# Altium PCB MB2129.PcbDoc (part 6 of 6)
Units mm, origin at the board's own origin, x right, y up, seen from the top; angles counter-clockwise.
Board outline 70 x 133.34 mm, 6 copper layers (Top Layer, Signal Layer 1, Signal Layer 2, Signal Layer 3, Signal Layer 4, Bottom Layer), stack 1.57 mm thick; 377 components, 289 nets, 1482 pads, 1373 vias.
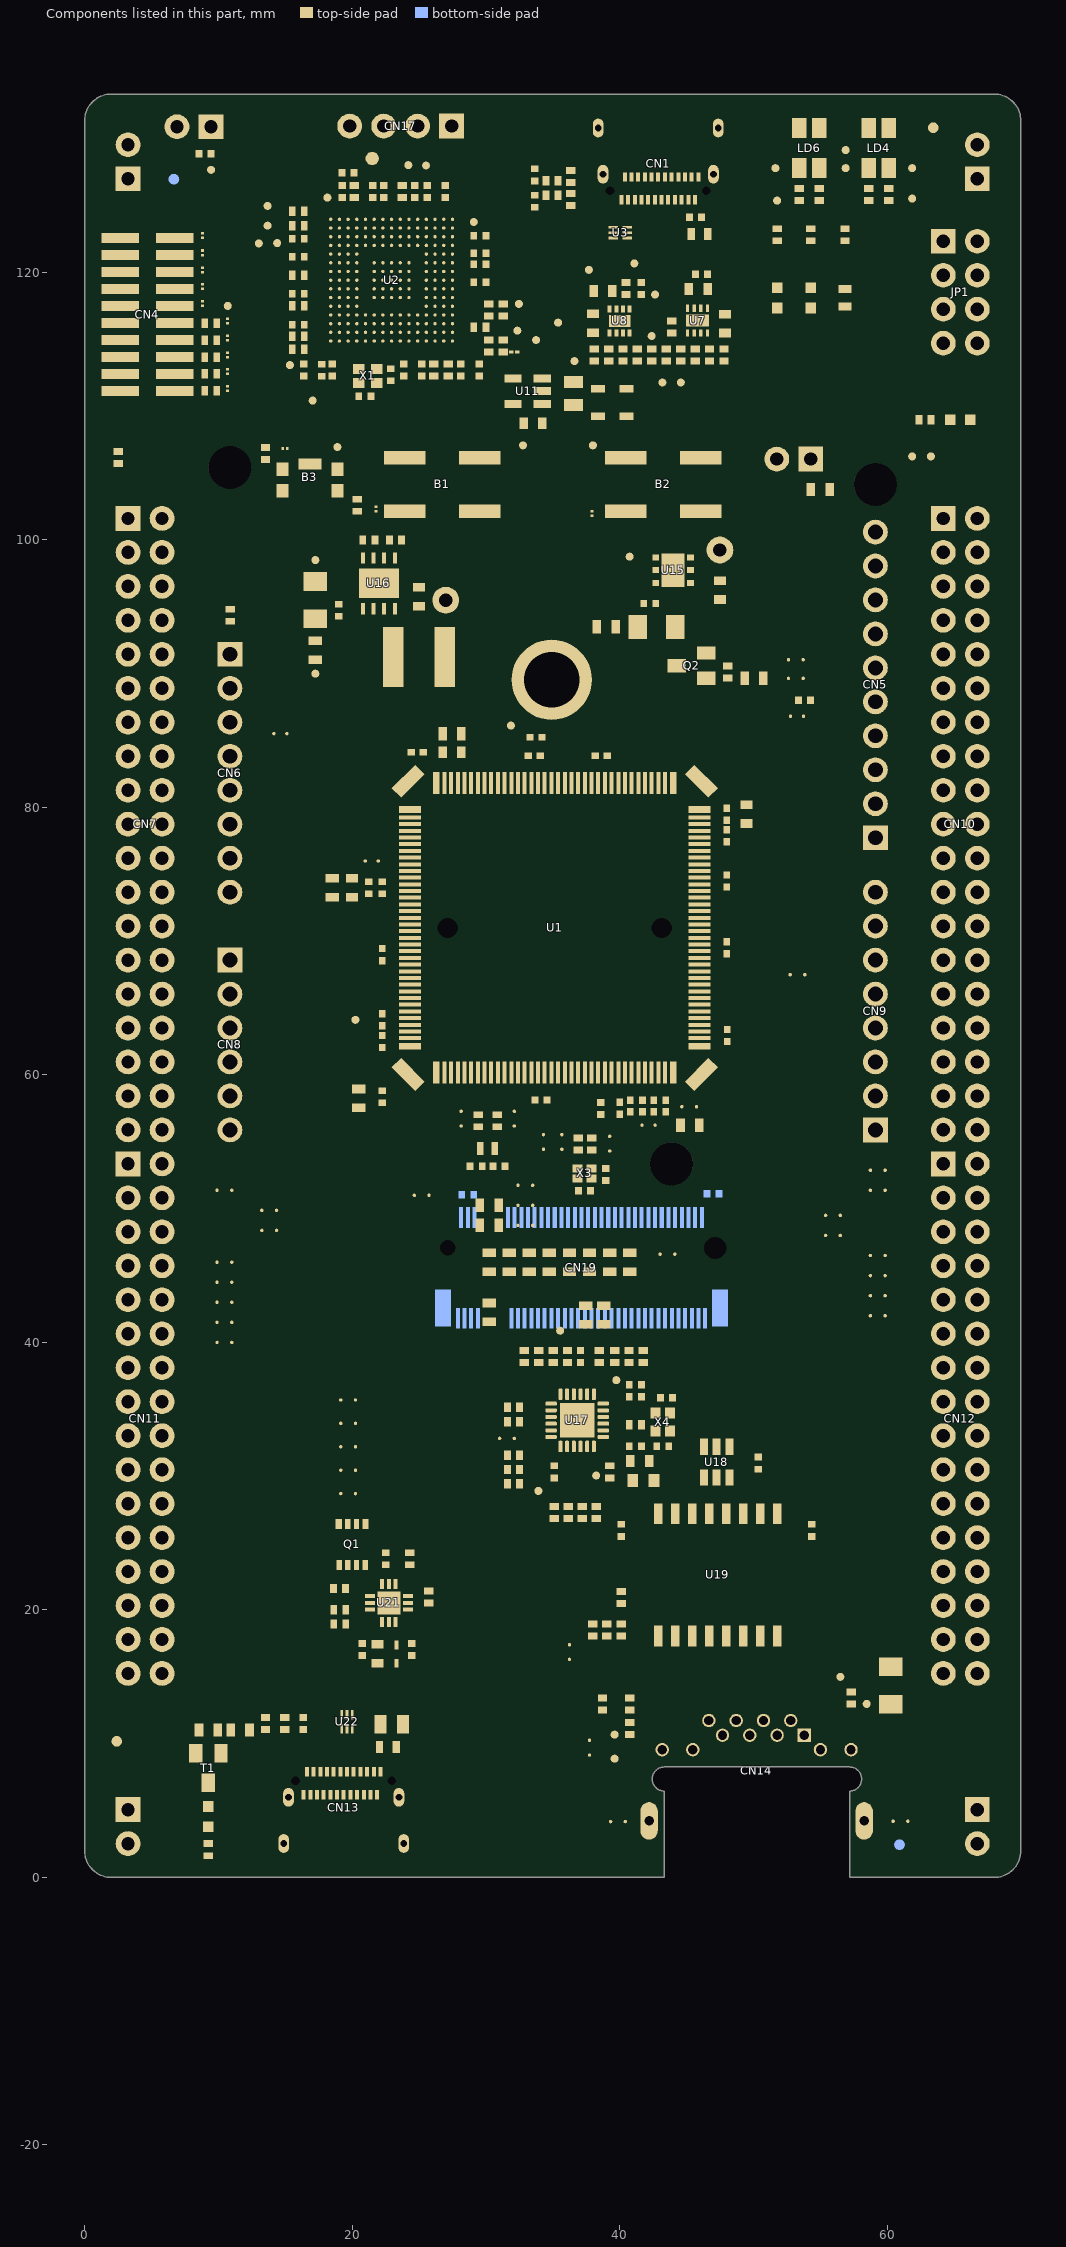
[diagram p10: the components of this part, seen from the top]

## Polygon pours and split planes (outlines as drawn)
GND on Top Layer "GND" (solid, remove dead copper, pour order 49): 38.349,-2.04 38.349,12.46 62.324,12.46 62.324,-2.04 72.124,-2.04 72.124,135.36 -1.001,135.36 -1.001,-2.04
VDD_MCU on Top Layer "VDDIO1_4_L01_P-001" (solid, remove dead copper, pour order 1): 49.75,80 50.25,80.5 50.25,81.75 50,82 49,82 48.75,81.75 48.75,80.5 49.25,80
NetC34_2 on Top Layer "NetC18_2" (solid, remove dead copper, pour order 9): 39.15,111.613 38.188,112.575 33.475,112.575 31.375,110.475 31.375,109.875 32.675,109.875 32.675,110.875 33.575,111.775 35.425,111.775 35.85,111.35 37.285,111.35 37.75,110.885 37.75,109.08 37.85,108.98 38.91,108.98 39.15,109.22
NetC43_2 on Top Layer "NetC30_2" (solid, remove dead copper, pour order 17): 39.5,93.25 40,92.75 42,92.75 42,96 42.6,96.6 42.95,96.6 42.95,97.95 41.45,97.95 39.5,96
GND on Top Layer "VDDIO1_4_L01_P-001" (solid, remove dead copper, pour order 48): 24.25,94.5 23,94.5 23,95.5 20.5,95.5 20,95 18.75,95 18.75,99 21,99 21,98 24.25,98
NetL2_1 on Top Layer "VDDIO1_4_L01_P-001" (solid, remove dead copper, pour order 2): 22.25,95.25 22.25,89.5 23.75,89.5 23.75,93.75 23.25,94.25 22.75,94.25 22.55,94.45 22.55,95.25
NetC44_2 on Top Layer "VDDIO1_4_L01_P-001" (solid, remove dead copper, pour order 47): 16.75,92.25 16.5,92.5 16.5,94.5 19.75,94.5 20,94.25 21.25,94.25 21.45,94.45 21.45,95.25 21.75,95.25 21.75,93.25 20.75,92.25
3V3 on Top Layer "5V_VIN" (solid, remove dead copper, pour order 18): 48.103,96.6 45.05,96.6 45.05,97.95 45.7,97.95 46.5,98.75 46.5,99.75 47.25,100.5 49.798,100.5 50.388,99.91 50.388,98.885
5V_VIN on Top Layer "5V_VIN" (solid, remove dead copper, pour order 15): 26,96.25 25.25,95.5 25,95.5 24.75,95.25 24.75,94.25 26.25,92.75 26.25,90.037 27.508,90.037 27.508,93.258 28,93.75 28,98.125 27.875,98.25 26.25,98.25 26,98
3V3 on Top Layer "3V3" (solid, remove dead copper, pour order 41): 0.675,85.902 2.793,85.902 2.793,68.875 0.675,68.875 0.675,85.899
5V_UCPD on Top Layer "5V_UCPD" (solid, remove dead copper, pour order 40): 21.7,20.875 21.7,21.825 20.525,23 20.525,23.75 18.825,23.75 18.825,22.651 20.601,20.875
5V on Top Layer "VIN" (solid, remove dead copper, pour order 31): 36.095,94.106 36.32,94.331 38.261,94.331 38.48,94.112 38.48,93.112 38.225,92.856 36.295,92.856 36.095,93.056
VIN on Top Layer "VIN" (solid, remove dead copper, pour order 14): 15.25,91.25 15.5,91.5 17.5,91.5 17.75,91.25 17.75,90 17.25,89.5 15.75,89.5 15.25,90
3V3_STLK on Top Layer "3V3_STLK" (solid, remove dead copper, pour order 12): 33.575,110.475 34.875,110.475 35.17,110.18 35.17,106.945 34.9,106.675 33.65,106.675 33.425,106.9 33.425,108.075 33.575,108.225
VBUS_STLK on Top Layer "VBUS_STLK" (solid, remove dead copper, pour order 8): 39.99,111.57 40.595,112.175 42.45,112.175 42.75,111.875 42.75,110.775 42.477,110.502 40.518,110.502 39.99,111.03
5V on Top Layer "5V" (solid, remove dead copper, pour order 7): 41.497,109.073 41.05,109.52 39.99,109.52 39.683,109.213 39.683,107.405 40,107.088 41.213,107.088 41.497,107.372
5V_STLK on Top Layer "5V_STLK" (solid, remove dead copper, pour order 6): 48.019,116.006 47.112,116.006 46.831,115.725 46.45,115.725 46.45,114.866 47.366,114.866 47.475,114.975 49.525,114.975 49.85,115.3 49.85,116.5 49.7,116.65 48.663,116.65
VBUS_STLK on Top Layer "VBUS_STLK" (solid, remove dead copper, pour order 5): 46.425,117.763 46.218,117.97 46.218,120.668 46.55,121 48.4,121 48.625,120.775 48.625,119.7 48.375,119.45 47.3,119.45 47.1,119.25 47.1,117.345 46.83,117.075 46.425,117.075
5V_STLK on Top Layer "5V_STLK" (solid, remove dead copper, pour order 4): 37.806,116.006 38.712,116.006 38.994,115.725 39.9,115.725 39.891,115.722 39.891,114.866 38.459,114.866 38.35,114.975 36.3,114.975 35.975,115.3 35.975,116.5 36.125,116.65 37.162,116.65
VBUS_STLK on Top Layer "VBUS_STLK" (solid, remove dead copper, pour order 3): 39.775,120.425 39.575,120.625 38.412,120.625 38.243,120.456 38.243,119.515 39.1,118.658 39.1,118.4 39.1,117.025 39.91,117.025 39.91,118.04 39.775,118.175
GND on Bottom Layer "C" (solid, remove dead copper, pour order 39): 38.4,-1.825 38.4,12.675 62.375,12.675 62.375,-1.825 72.175,-1.825 72.175,135.575 -0.95,135.575 -0.95,-1.825
SHGND on Bottom Layer "SHGND_L06_P019" (solid, remove dead copper, pour order 19): 41.547,13.675 59.275,13.675 59.275,0 41.647,0 41.547,0.004
3V3 on Bottom Layer "3V3" (solid, remove dead copper, pour order 32): 55.236,104.75 52.6,104.75 52.6,121.276 50.875,123.001 50.875,124.21 51.605,124.94 57.655,124.94 58.122,124.472 58.122,115.422 55.225,112.525 55.225,108.55
3V3 on Bottom Layer "3V3" (solid, remove dead copper, pour order 34): 0.675,85.902 2.793,85.902 2.793,68.875 0.675,68.875 0.675,85.899
5V_STLK on Bottom Layer "5V_STLK" (solid, remove dead copper, pour order 27): 62.45,123.85 63.775,125.175 68.509,125.175 69.325,124.359 69.325,92.403 66.072,92.403 65.159,93.316 65.159,120.556 64.739,120.975 62.975,120.975 62.45,121.5
GND on Signal Layer 1 "GND" (solid, remove dead copper, pour order 37): 38.4,-1.825 62.375,-1.825 72.175,-1.825 72.175,135.575 -0.95,135.575 -0.95,-1.825
AGND on Signal Layer 1 "AGND" (solid, remove dead copper, pour order 0): 39.25,61 41.05,61 41.05,59.325 41.15,59.225 42.325,59.225 42.425,59.125 42.425,57.023 42.748,56.7 42.745,56.697 42.745,55.35 39.781,55.35 39.25,55.881 39.25,59.475
5V on Signal Layer 3 "5V" (solid, remove dead copper, pour order 29): 11.65,95.6 11.275,95.225 11.275,94 12.271,93.004 12.271,83.661 11.21,82.6 4.625,82.6 4.625,80 14.725,80 14.725,91.05 15.425,91.75 18,91.75 18.575,91.175 18.575,89.025 31.025,89.025 34.75,92.75 38.75,92.75 41.113,95.1 41.113,105.093 42.396,106.375 47.375,106.375 49.3,108.3 68.95,108.3 68.95,123.6 65.725,123.6 65.725,113.275 62.8,110.35 48.275,110.35 46.525,108.6 39.933,108.6 38.75,107.417 38.75,98.15 36.2,95.6 29.35,95.6 28,94.25 26.25,94.25 24.9,95.6
3V3 on Signal Layer 3 "3V3" (solid, remove dead copper, pour order 38): 38.435,-0.074 38.435,14.426 62.41,14.426 62.41,-0.074 72.21,-0.074 72.21,137.326 -0.915,137.326 -0.915,-0.074
3V3_STLK on Signal Layer 3 "3V3_STLK" (solid, remove dead copper, pour order 28): 58.575,132.2 17.425,132.2 14.042,128.817 14.042,114.708 22.775,105.975 34.681,105.975 35.5,106.794 35.5,109.925 32.975,112.45 32.975,120.15 40.3,127.475 57.3,127.475 58.869,129.044 58.869,131.906
GND on Signal Layer 3 "NONET_L01_P-001" (solid, remove dead copper, pour order 50): 54.625,31.375 69.75,31.375 69.75,1.03 68.72,0 62.375,0 62.375,17.25 54.625,17.25
VDD_MCU on Signal Layer 3 "VDD_MCU" (solid, remove dead copper, pour order 25): 49.359,62.884 49.359,57.581 47.667,55.889 42.364,55.889 37.25,50.775 30.324,50.775 28.624,52.475 23.9,52.475 17.456,58.919 17.456,71.9 17.1,72.256 17.1,74.833 18.7,76.433 18.7,88.873 41.273,88.873 50.263,97.862 50.263,106.475 50.513,106.725 52.875,106.725 53.025,106.575 53.025,66.55
5V_UCPD on Signal Layer 3 "5V_UCPD" (solid, remove dead copper, pour order 30): 20.85,21.641 20.474,21.265 19.59,21.265 19.448,21.127 13.925,15.603 13.925,9.371 11.275,9.371 11.275,33.813 15.462,38 56.071,38 60.331,42.26 60.331,102.469 58.9,103.9 58.9,108.2 70,108.2 70,31.933 19.325,31.933 18.55,31.125 18.55,25.372 20.85,23.072
VIN on Signal Layer 3 "VIN" (solid, remove dead copper, pour order 26): 18.473,76.524 16.825,74.876 16.825,71.968 16.225,71.968 4.948,71.968 4.199,72.717 4.199,74.349 4.875,75.025 12.6,75.025 14.9,77.325 14.9,90.966 15.434,91.5 18,91.5 18.473,91.027 18.473,88.973
5V_VIN on Signal Layer 3 "5V_VIN" (solid, remove dead copper, pour order 20): 25.5,95 26,94.5 28,94.5 29.342,95.842 36.242,95.842 38.625,98.225 38.625,107.467 39.908,108.75 46.525,108.75 48.25,110.475 62.725,110.475 65.625,113.375 65.625,121 55.825,121 49.1,114.275 42.98,114.275 42.98,110.88 42.475,110.375 35.5,110.375 35.5,106.675 34.7,105.875 25.5,105.875
VBUSc on Signal Layer 3 "VBUSc" (solid, remove dead copper, pour order 22): 21.887,7.538 21.84,7.49 21.84,6.896 21.19,6.246 16.904,6.246 14.042,9.108 14.042,15.515 18.917,20.433 19.655,21.125 20.525,21.125 20.975,21.575 20.975,23.1 18.675,25.4 18.675,27.45 18.885,27.66 21.365,27.66 24.35,24.675 24.35,10
VBUS_STLK on Signal Layer 3 "VBUS_STLK" (solid, remove dead copper, pour order 23): 40.325,127.35 49.425,127.35 49.425,119.125 38.075,119.125 35.5,116.55 35.5,114.701 35.926,114.275 42.904,114.275 42.904,110.929 42.477,110.502 34.848,110.502 33.075,112.275 33.075,120.1
NetC88_2 on Signal Layer 3 "NetC79_2" (solid, remove dead copper, pour order 33): 33.466,31.825 45.8,31.825 54.125,31.825 54.125,25.818 52.245,25.818 52.245,28.125 42.42,28.125 42.42,25.95 35.357,25.95 33.466,27.842
5V_STLK on Signal Layer 3 "5V_STLK" (solid, remove dead copper, pour order 21): 49.06,114.4 55.785,121.125 66.15,121.125 66.15,123.775 59.283,123.775 58.683,123.175 49.573,123.175 49.573,119.016 38.141,119.016 35.625,116.5 35.625,114.78 36.005,114.4
GND on Signal Layer 4 "GND" (solid, remove dead copper, pour order 35): 38.4,-1.825 38.4,12.675 62.375,12.675 62.375,-1.825 72.175,-1.825 72.175,135.575 -0.95,135.575 -0.95,-1.825
GND on Signal Layer 2 "GND" (solid, remove dead copper, pour order 36): 38.4,-1.825 62.375,-1.825 72.175,-1.825 72.175,135.575 -0.95,135.575 -0.95,-1.825

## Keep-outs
Top Layer:
  circle w1.5: c66.1,105.725 r0.75
  circle w1.5: c29.325,18.7 r0.75
  circle w1.5: c10.8,98.375 r0.75
  circle w1.5: c15.4,71.175 r0.75
  circle w1.5: c65.55,10.125 r0.75
  circle w1.5: c4.525,10.125 r0.75
  circle w1.5: c59.125,49.05 r0.75
  circle w1.5: c10.8,49.05 r0.75
  circle w1.5: c54.325,71.125 r0.75
Bottom Layer:
  circle w1.5: c66.1,105.725 r0.75
  circle w1.5: c10.8,98.375 r0.75
  circle w1.5: c15.4,71.175 r0.75
  circle w1.5: c54.325,71.125 r0.75
  circle w1.5: c59.125,49.05 r0.75
  circle w1.5: c10.8,49.05 r0.75
  circle w1.5: c4.525,10.125 r0.75
  circle w1.5: c29.325,18.7 r0.75
  circle w1.5: c65.55,10.125 r0.75
  region: 8.125,105.429 8.125,105.437 cw(c10.858,105.437) 10.858,108.17 cw(c10.858,105.412) 13.616,105.412 cw(c10.879,105.412) 10.879,102.675 cw(c10.879,105.429)
  region: 56.385,104.159 56.385,104.167 cw(c59.118,104.167) 59.118,106.9 cw(c59.118,104.142) 61.876,104.142 cw(c59.139,104.142) 59.139,101.405 cw(c59.139,104.159)
  region: 41.145,53.359 41.145,53.367 cw(c43.878,53.367) 43.878,56.1 cw(c43.878,53.342) 46.636,53.342 cw(c43.899,53.342) 43.899,50.605 cw(c43.899,53.359)

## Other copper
Top Layer:
  pour cut-out: 32.309,123.767 31.582,124.494 ccw(c30.3,123.212) 30.3,125.025 27.679,125.025 ccw(c27.679,124.171) 27.075,124.775 ccw(c27.618,124.232) 26.85,124.232 26.85,123.654 ccw(c27.704,123.654) 27.1,123.05 27.244,122.906 ccw(c27.588,123.251) 27.588,122.763 ccw(c27.588,123.246) 27.93,122.905 28.212,123.187 ccw(c27.998,123.4) 28.3,123.4 cw(c29.085,123.4) 28.53,123.955 28.575,124 cw(c28.85,123.725) 28.85,124.114 30.135,124.114 cw(c30.135,122.717) 31.123,123.705 31.582,123.246
  pour cut-out: 19,18.48 19.15,18.48 19.15,19.213 19.139,19.224 19,19.224
  pour cut-out: 18.875,22.15 19.075,22.15 19.225,22 19.225,21.275 19.371,21.129 19.975,21.129 19.975,20.654 19.816,20.495 19.16,20.495 19.08,20.575 18.875,20.575
  pour cut-out: 26.2,21.375 26.195,21.37 26.195,20.15 24.875,20.15 24.67,20.355 24.67,21.295 24.8,21.425
  pour cut-out: 34.645,29.42 34.645,26.894 35.089,26.45 35.7,26.45 35.7,28.925 35.2,29.425
  pour cut-out: 44.325,34.1 44.245,34.02 44.245,32.045 43.925,31.725 41.975,31.725 41.55,31.3 41.225,31.3 41.225,30.05 41.025,29.85 40.525,29.85 40.175,30.2 39.2,30.2 39.1,30.1 39.1,28.48 38.65,28.03 37.92,28.03 37.45,28.5 37.45,30.4 39.7,32.65 41.02,32.65 41.975,32.65 41.975,33.25 41.845,33.38 39.82,33.38 39.7,33.5 39.7,34.325 40.1,34.725 43.125,34.725 43.75,34.1
  pour cut-out: 31.702,39.426 32.004,39.426 32.405,39.025 32.405,38.125 37.45,38.125 39.009,36.566 39.009,35.253 39.437,34.825 40,34.825 40,35.416 41.305,36.721 41.305,38.125 42.245,38.125 42.245,41.327 41.934,41.638 41.432,41.638 40.694,40.9 37.775,40.9 37.675,40.8 37.675,40.225 38.05,39.85 38.05,39.275 37.85,39.075 36.3,39.075 35.8,39.575 35.8,40.435 35.51,40.725 32.325,40.725 31.7,40.1 31.7,40
  pour cut-out: 31.25,35.62 31.25,28.955 33.804,28.955 33.925,29.076 33.925,35.35 33.655,35.62 32.9,35.62
  pour cut-out: 32.05,45.725 37.325,45.725 37.325,44.164 37.011,43.85 32.05,43.85
  pour cut-out: 40.25,56.775 40.775,56.25 41.548,56.25 41.548,58.022 41.445,58.125 40.425,58.125 40.25,57.95
  pour cut-out: 35.9,56.35 37.625,56.35 37.87,56.595 38.23,56.595 38.756,56.069 38.756,55.534 38.222,55 35.9,55
  pour cut-out: 32.125,58.1 30.975,58.1 30.85,57.975 30.85,57.125 31.245,56.73 32.358,56.73
  pour cut-out: 27.989,58.1 29.875,58.1 29.875,56.675 27.903,56.675
  pour cut-out: 30.5,49.975 30.5,48.38 30.76,48.12 34.07,48.12 34.33,48.38 34.33,50.12 34.2,50.25 30.775,50.25 30.625,50.1
  pour cut-out: 28.7,50 28.225,49.525 28.225,48.75 29.975,48.75 29.975,50
  pour cut-out: 22.5,23.12 22.6,23.02 22.6,22.325 21.384,22.325 20.967,22.741 20.975,22.749 20.975,23.125
  pour cut-out: 16.37,6.32 16.365,6.325 15.275,6.325 15.275,6.65 15.24,6.685 15.48,6.925 16.4,6.925
  pour cut-out: 25.35,62.55 28.472,62.55 29.512,61.51 29.769,61.51 29.769,60.969 29.5,60.7 25.5,60.7 25.325,60.875 25.35,60.9 25.35,62.4
  pour cut-out: 26.214,67.25 26.178,67.214 26.178,66.25 29.047,66.25 29.045,66.252 29.045,67.171
  pour cut-out: 4.082,71.772 4.229,71.625 6.198,71.625 6.87,70.954 6.87,67.477 6.668,67.275 4.561,67.275 4.082,67.754
  pour cut-out: 20.2,74.7 20.2,73.225 20.575,72.85 23.555,72.85 23.985,73.28 23.985,73.965 23.25,74.7
  pour cut-out: 21.73,79.929 21.73,77.028 21.858,76.9 23.5,76.9 23.5,79.6 23.171,79.929
  pour cut-out: 50.947,84.301 50.947,82.978 51.348,82.577 51.8,82.577 51.8,84.175 51.674,84.301
  pour cut-out: 50.145,78.628 50.625,78.628 50.625,78.325 50.617,78.317 50.145,78.317
  pour cut-out: 43.268,70.1 45.15,70.1 45.15,70.825 44.525,71.45 43.475,71.45 43.275,71.25
  pour cut-out: 27.295,84 27.725,84 27.725,84.895 27.735,84.905 28.615,84.905 28.615,83.56 28.65,83.525 29.31,83.525 29.75,83.085 29.75,82.65 27.25,82.65
  pour cut-out: 47.297,90.27 47.297,89.055 48.91,89.055 49.03,89.175 49.03,90.175 48.755,90.45 47.525,90.45
  pour cut-out: 41.112,98.526 41.112,97.963 41.2,97.875 41.405,98.08 43.115,98.08 43.15,98.045 43.15,96.5 42.725,96.5 42.146,95.921 42.146,95.803 42.172,95.803 42.245,95.73 42.575,95.73 42.575,95.925 43,96.35 43.45,96.35 43.45,98.181 43.105,98.526
  pour cut-out: 21.33,98.105 21.33,100.428 21.372,100.47 24.075,100.47 24.395,100.15 24.395,98.911 24.164,98.68 23.552,98.68 22.977,98.105 22.93,98.105
  pour cut-out: 18.26,94.92 18.34,95 20.135,95 20.53,95.395 21.33,95.395 21.32,95.385 21.32,94.504 19.93,94.504 19.804,94.63 18.26,94.63
  pour cut-out: 4.291,81.428 4.291,83.692 6.831,83.692 7,83.861 7,89.55 6.6,89.95 2.909,89.95 2.201,89.242 2.201,86.494 3.042,85.654 3.042,81.483 3.1,81.425
  pour cut-out: 43.284,111.355 44.749,111.355 44.97,111.576 44.97,113.075 44.92,113.125 43.275,113.125
  pour cut-out: 44.75,116.275 44.725,116.25 44.45,116.25 44.45,116.145 44.035,115.73 44.051,115.715 44.051,115.22 44.93,115.22 44.95,115.2 44.95,116.075
  pour cut-out: 45.485,125.44 45.51,125.415 45.51,124.765 46.125,124.15 46.125,123 44.209,123 43.849,123.36 43.278,123.36 43.2,123.438 43.2,125.005 43.635,125.44
  pour cut-out: 28.125,111.795 29.3,111.795 29.5,111.995 29.5,112.895 28.38,112.895 28.125,112.895
  pour cut-out: 15.92,112.375 17.88,112.375 18.005,112.5 18.005,113.345 17.55,113.8 15.17,113.8 15.17,113.142 15.577,112.736
  pour cut-out: 31.85,116.295 31.85,116.15 33.05,114.95 33.45,114.95 33.45,114.68 32.82,114.05 31.22,114.05 30.525,114.745 30.525,116.3
  pour cut-out: 29.7,124.225 29.7,123.405 29.875,123.23 29.875,119.146 30.446,118.575 31.7,118.575 31.7,118.487 31.85,118.337 31.85,116.295 31.65,116.495 29.68,116.495 29.275,116.9 29.4,117.025 29.4,124.225
  pour cut-out: 15.166,125.025 18.25,125.025 18.25,124.5 17.6,123.85 15.175,123.85
  pour cut-out: 15.776,123.15 15.65,123.024 15.65,121.585 15.78,121.455 16.17,121.455 16.17,123.146 16.166,123.15
  pour cut-out: 15.675,117.925 15.07,117.32 15.07,116.375 16.15,116.375 16.15,117.925
  pour cut-out: 39.25,19.7 39.25,22.625 52.225,22.625 52.225,18.43 62.375,18.43 62.375,0 38.447,0 38.447,15.678 37.175,16.95 37.175,19.7
  pour cut-out: 27.23,126.245 29.1,124.375 29.1,114.35 20.25,114.35 20.25,126.245
  text "1" at 26.793,1.334 h2 r90
  text ".Layer_Name" at 0.747,-16.422 h3
  text ".GTL" at 42.441,-16.422 h3
Signal Layer 1:
  text "2" at 26.793,2.584 h2 r90
  text ".Layer_Name" at 0.747,-16.422 h3
  text ".G1" at 42.441,-16.422 h3
Signal Layer 2:
  pour cut-out: 38.447,17.125 62.375,17.125 62.375,0 38.447,0
  text "3" at 26.793,4.084 h2 r90
  text ".Layer_Name" at 0.672,-16.422 h3
  text ".G2" at 42.366,-16.422 h3
Signal Layer 3:
  pour cut-out: 38.447,17.125 62.375,17.125 62.375,0 38.447,0
  text "4" at 26.793,6.334 h2 r90
  text ".Layer_Name" at 0.735,-16.418 h3
  text ".G3" at 42.43,-16.418 h3
Signal Layer 4:
  pour cut-out: 38.4,17.125 62.328,17.125 62.328,0 38.4,0
  text "5" at 26.793,7.834 h2 r90
  text ".Layer_Name" at 0.747,-16.422 h3
  text ".G4" at 42.441,-16.422 h3
Bottom Layer:
  pour cut-out: 30.086,46.98 31.829,46.98 31.829,44.889 32.172,44.546 32.796,44.546 34,45.75 35.65,45.75 35.65,45.725 36.329,45.046 36.329,44.23 36.325,44.226 36.325,43.55 36.346,43.55 36.61,43.285 37.495,44.17 38.795,44.17 38.795,45.347 38.49,45.652 38.49,47.435 36.873,49.052 29.555,49.052 29.555,47.511 29.915,47.151
  pour cut-out: 25.894,64.353 25.88,64.34 24.545,64.34 24.545,61.355 25.286,60.614 26.2,60.614
  pour cut-out: 38.506,13.601 38.506,17.125 62.256,17.125 62.256,13.601
  pour cut-out: 38.447,17.125 41.381,17.125 41.381,0 38.447,0
  pour cut-out: 62.365,0 59.431,0 59.431,17.125 62.365,17.125
  text "6" at 26.793,9.334 h2 r90
  text ".GBL" at 31.238,-16.454 h3
  text ".Layer_Name" at 72.552,-16.454 h3
Multi-Layer:
  pour cut-out: 42.42,28.125 42.42,17.125 52.245,17.125 52.245,28.125
  pour cut-out: 25.175,1.1 27.175,1.1 27.175,9.6 25.175,9.6

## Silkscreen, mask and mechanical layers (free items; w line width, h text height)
Top Overlay:
  circle w0.3: c51.95,102.775 r1.485
  region: 54.025,102.9 53.425,102.9 53.425,102.625 54.025,102.625
  rectangle: 49.875,102.625 50.475,102.9
  lines w0.12: 42.2,44.575 41.875,44.9 ; 42.2,45.225 41.875,44.9 ; 45.55,44.9 41.875,44.9 ; 45.55,45.875 45.55,43.3 54.425,43.3 ; 57.1,104.6 57.1,104.9 58.325,106.125 60.225,106.125 61,105.35 ; 0.625,115.494 0.625,118.25 1.12,118.25 1.12,125 8.28,125 8.28,108.875 1.12,108.875 1.12,115.494 0.625,115.494
  lines w0.25: 58.622,107.852 69.545,107.852 69.545,124.617 58.622,124.617 58.622,107.852
  lines w0.254: 50.324,115 58.622,115 ; 50.324,115 50.324,107.852 58.622,107.852 58.622,115 ; 50.324,115 58.622,115 ; 50.324,115 50.324,124.616 58.622,124.616 58.622,115
  text "PWR_STATUS" at 47.975,132.15 h1.4
  text "COM" at 57.85,132.075 h1.52
  text "GND" at 2,131.35 h1.52
  text "GND" at 65.226,131.328 h1.52
  text "STLK RST" at 11.55,129.7 h1.52
  text "USB STLINK" at 32.725,129.1 h1.52
  text "RESERVED" at 22.5,128.625 h1.4
  text "MIPI20" at 2.725,123.725 h1.52
  text "STLK" at 59.384,121.822 h1.4
  text "VIN" at 60.4,119.282 h1.4
  text "NRST" at 11.425,117.075 h1.5
  text "EXT" at 60.146,116.742 h1.4
  text "User LEDs" at 51.375,115.6 h1.4
  text "5V_SELECT" at 69.163,114.71 h1.4 r90
  text "USB1" at 59.375,114.1 h1.4
  text "5V" at 66.05,112.2 h1.4
  text "PWR_ON" at 63.3,110.05 h1.4
  text "BOOT0" at 14.85,107.6 h1.4
  text "USER" at 25,107.6 h1.52
  text "RESET" at 41.2,107.6 h1.52
  text "3V3" at 55.845,106.05 h1.4
  text "VDD MCU" at 47.7,104.9 h1.4
  text "IDD" at 47.775,102.65 h1.4
  text "A" at 51.225,102.05 h2.5
  text "SCL" at 54.916,100.15 h1.02
  text "3V3" at 48.425,100.067 h1.5
  text "SDA" at 54.829,97.61 h1.02
  text "AREF" at 54.069,95.07 h1.02
  text "5V_VIN" at 28.55,94.991 h1.5
  text "GND" at 54.819,92.53 h1.02
  text "NC" at 12.525,90.85 h1.02
  text "SCK" at 54.819,89.99 h1.02
  text "IOREF" at 12.45,88.506 h0.97
  text "MISO" at 54.768,87.352 h1.02
  text "NRST" at 12.475,86.4 h1
  text "~ MOSI" at 52.542,84.801 h1.7
  text "DIGITAL ~ PWM" at 62.307,83.42 h2 r90
  text "3V3" at 12.45,83.325 h1.02
  text "~ NSS" at 53.246,82.261 h1.7
  text "5V" at 12.45,80.8 h1.02
  text "POWER" at 8.967,79.771 h2 r90
  text "~ D9" at 54.416,79.721 h1.7
  text "GND" at 12.45,78.275 h0.97
  text "D8" at 55.83,77.29 h1.02
  text "GND" at 12.45,75.75 h0.97
  text "D7" at 55.83,73.162 h1.02
  text "VIN" at 12.45,72.975 h1.02
  text "~ D6" at 54.418,70.514 h1.7
  text "A0" at 12.634,68.033 h1.02
  text "~ D5" at 54.41,67.974 h1.7
  text "A1" at 12.634,65.686 h1.02
  text "D4" at 55.781,65.542 h1.02
  text "A2" at 12.634,63.029 h1.02
  text "~ D3" at 54.418,62.894 h1.7
  text "A3" at 12.634,60.591 h1.02
  text "D2" at 55.83,60.462 h1.02
  text "ANALOG" at 8.967,58.697 h2 r90
  text "A4" at 12.634,58.076 h1.02
  text "DIGITAL ~ PWM" at 62.307,58.02 h2 r90
  text "TX" at 55.936,57.922 h1.02
  text "A5" at 12.634,55.485 h1.02
  text "RX" at 55.83,55.382 h1.02
  text "32K" at 24.35,54.075 h1.4
  text "48M" at 41.025,50.125 h1.4
  text "J" at 15.95,40.225 h17.78
  text "MB2129D" at 16.45,39.35 h2.54
  text "L" at 54.1,32.55 h14
  text "ETH1" at 48.375,12.925 h1.52
  text "GND" at 1.853,7.122 h1.52
  text "GND" at 65.226,7.122 h1.52
  text "VBUS" at 11.025,3 h1.4 r90
  text "USB1" at 14.1,2.65 h1.52 r90
  text ".Layer_Name" at 0.747,-16.422 h3
  text ".GTO" at 42.441,-16.422 h3
Bottom Overlay:
  drawing of 66 lines, arcs and shapes, not listed
  text "GND" at 4.901,131.328 h1.52
  text "GND" at 68.274,131.328 h1.52
  text "C" at 57.5,113.875 h9
  text "F" at 26.791,113.25 h12
  text "S" at 35.886,113.25 h8
  text "G" at 47.625,113.25 h11
  text "H" at 31.375,104.6 h12
  text "I" at 42.975,104.2 h11
  text "CN10" at 67.049,104.12 h1.5
  text "CN7" at 5.852,104.02 h1.5
  text "1" at 63.743,102.948 h1.5 r270
  text "2" at 5.318,102.83 h1.5 r270
  text "2" at 66.168,102.83 h1.5 r270
  text "1" at 2.743,102.748 h1.5 r270
  text "CN5" at 57.556,102.17 h1.5
  text "PC10" at 1.725,100.975 h1.1 r315
  text "PC9" at 62.41,100.975 h1.1 r315
  text "PC11" at 8.45,100.95 h1.1 r315
  text "PF6" at 69.41,100.95 h1.1 r315
  text "SCL" at 57.523,100.15 h1.02
  text "PC12" at 1.725,98.435 h1.1 r315
  text "PF5" at 62.41,98.435 h1.1 r315
  text "PF15" at 8.45,98.41 h1.1 r315
  text "PD14" at 69.41,98.41 h1.1 r315
  text "SDA" at 57.523,97.61 h1.02
  text "3V3" at 1.725,95.895 h1.1 r315
  text "PG6" at 62.41,95.895 h1.1 r315
  text "PD15" at 69.41,95.87 h1.1 r315
  text "5V_EXT" at 8.825,95.295 h1.1 r315
  text "AREF" at 57.523,95.07 h1.02
  text "5V" at 69.425,94.2 h1.1 r315
  text "CN6" at 12.877,93.57 h1.5
  text "GND" at 8.45,93.33 h1.1 r315
  text "AREF" at 62.925,92.9 h1.1 r315
  text "STLK" at 69.4,92.8 h1.1 r315
  text "1" at 10.443,92.748 h1.5 r270
  text "GND" at 57.523,92.53 h1.02
  text "BOOT0" at 2.325,92.425 h1.1 r315
  text "NC" at 14.31,90.867 h1.02
  text "PG0" at 1.725,90.815 h1.1 r315
  text "GND" at 62.41,90.815 h1.1 r315
  text "PG1" at 8.45,90.79 h1.1 r315
  text "PE0" at 69.41,90.79 h1.1 r315
  text "SCK" at 57.523,89.99 h1.02
  text "IOREF" at 16.004,88.512 h0.97
  text "PB3" at 1.725,88.275 h1.1 r315
  text "PE12" at 62.41,88.275 h1.1 r315
  text "3V3" at 8.45,88.25 h1.1 r315
  text "NC" at 69.41,88.25 h1.1 r315
  text "MISO" at 57.523,87.352 h1.02
  text "NRST" at 16.017,86.407 h1
  text "PA13" at 1.725,85.735 h1.1 r315
  text "PE13" at 62.41,85.735 h1.1 r315
  text "NRST" at 8.45,85.71 h1.1 r315
  text "NC" at 69.41,85.71 h1.1 r315
  text "~ MOSI" at 57.65,84.806 h1.7
  text "DIGITAL ~ PWM" at 50.225,83.42 h2 r270
  text "3V3" at 15.113,83.332 h1.02
  text "PA14" at 1.725,83.195 h1.1 r315
  text "PE14" at 62.41,83.195 h1.1 r315
  text "3V3" at 8.45,83.17 h1.1 r315
  text "PE15" at 69.41,83.17 h1.1 r315
  text "~ NSS" at 57.65,82.266 h1.7
  text "5V" at 14.305,80.807 h1.02
  text "PA15" at 1.725,80.655 h1.1 r315
  text "PE11" at 62.41,80.655 h1.1 r315
  text "5V" at 8.45,80.63 h1.1 r315
  text "PB1" at 69.41,80.63 h1.1 r315
  text "POWER" at 17.56,79.771 h2 r270
  text "~ D9" at 57.65,79.726 h1.7
  text "GND" at 15.09,78.282 h0.97
  text "GND" at 1.725,78.115 h1.1 r315
  text "PF4" at 62.41,78.115 h1.1 r315
  text "GND" at 8.45,78.09 h1.1 r315
  text "GND" at 69.41,78.09 h1.1 r315
  text "D8" at 57.523,77.29 h1.02
  text "1" at 58.618,76.148 h1.5 r270
  text "GND" at 15.09,75.757 h0.97
  text "PG2" at 1.725,75.575 h1.1 r315
  text "PA9" at 62.41,75.575 h1.1 r315
  text "GND" at 8.45,75.55 h1.1 r315
  text "PF2" at 69.41,75.55 h1.1 r315
  text "D7" at 57.523,73.162 h1.02
  text "PA0" at 1.725,73.035 h1.1 r315
  text "PE9" at 62.41,73.035 h1.1 r315
  text "VIN" at 8.45,73.01 h1.1 r315
  text "PF14" at 69.41,73.01 h1.1 r315
  text "VIN" at 14.422,72.982 h1.02
  text "~ D6" at 57.65,70.518 h1.7
  text "PC14" at 1.725,70.495 h1.1 r315
  text "PF3" at 62.41,70.495 h1.1 r315
  text "PG4" at 8.45,70.47 h1.1 r315
  text "PB15" at 69.41,70.47 h1.1 r315
  text "1" at 10.218,69.823 h1.5 r270
  text "A0" at 14.315,68.04 h1.02
  text "~ D5" at 57.65,67.978 h1.7
  text "PC15" at 1.725,67.955 h1.1 r315
  text "PG15" at 62.41,67.955 h1.1 r315
  text "PA6" at 8.45,67.93 h1.1 r315
  text "PE10" at 69.41,67.93 h1.1 r315
  text "A1" at 13.88,65.693 h1.02
  text "D4" at 57.523,65.542 h1.02
  text "PH0" at 1.725,65.415 h1.1 r315
  text "PD3" at 62.41,65.415 h1.1 r315
  text "PA7" at 8.45,65.39 h1.1 r315
  text "PE8" at 69.41,65.39 h1.1 r315
  text "A2" at 14.315,63.036 h1.02
  text "~ D3" at 57.65,62.898 h1.7
  text "PH1" at 1.725,62.875 h1.1 r315
  text "PF1" at 62.41,62.875 h1.1 r315
  text "PA4" at 8.45,62.85 h1.1 r315
  text "AGND" at 69.41,62.85 h1.1 r315
  text "A3" at 14.315,60.598 h1.02
  text "D2" at 57.523,60.462 h1.02
  text "VBAT" at 1.725,60.335 h1.1 r315
  text "PA10" at 62.41,60.335 h1.1 r315
  text "PB0" at 8.45,60.31 h1.1 r315
  text "PF13" at 69.41,60.31 h1.1 r315
  text "ANALOG" at 17.56,58.697 h2 r270
  text "A4" at 14.364,58.083 h1.02
  text "DIGITAL ~ PWM" at 50.225,58.02 h2 r270
  text "TX" at 57.523,57.922 h1.02
  text "PC2" at 1.725,57.795 h1.1 r315
  text "PB4" at 62.41,57.795 h1.1 r315
  text "PF12" at 8.45,57.77 h1.1 r315
  text "PF8" at 69.41,57.77 h1.1 r315
  text "A5" at 14.315,55.492 h1.02
  text "RX" at 57.523,55.382 h1.02
  text "PC3" at 1.725,55.255 h1.1 r315
  text "PA8" at 62.41,55.255 h1.1 r315
  text "PF11" at 8.45,55.23 h1.1 r315
  text "PF9" at 69.41,55.23 h1.1 r315
  text "1" at 58.693,54.248 h1.5 r270
  text "PD11" at 1.725,52.715 h1.1 r315
  text "PB7" at 62.41,52.715 h1.1 r315
  text "NC" at 8.45,52.69 h1.1 r315
  text "PG10" at 69.41,52.69 h1.1 r315
  text "CN8" at 12.203,52.595 h1.5
  text "CN9" at 60.453,52.595 h1.5
  text "PD12" at 1.725,50.175 h1.1 r315
  text "PB6" at 62.41,50.175 h1.1 r315
  text "NC" at 8.45,50.15 h1.1 r315
  text "PG11" at 69.41,50.15 h1.1 r315
  text "PF7" at 1.725,47.635 h1.1 r315
  text "PG5" at 62.41,47.635 h1.1 r315
  text "NC" at 8.45,47.61 h1.1 r315
  text "PG9" at 69.41,47.61 h1.1 r315
  text "PD13" at 1.725,45.095 h1.1 r315
  text "PG13" at 62.41,45.095 h1.1 r315
  text "NC" at 8.45,45.07 h1.1 r315
  text "PD7" at 69.41,45.07 h1.1 r315
  text "PE7" at 1.725,42.555 h1.1 r315
  text "NC" at 62.41,42.555 h1.1 r315
  text "NC" at 8.45,42.53 h1.1 r315
  text "NC" at 69.41,42.53 h1.1 r315
  text "PD5" at 1.725,40.015 h1.1 r315
  text "MEM_LED1" at 62.41,40.015 h1.1 r315
  text "NC" at 8.45,39.99 h1.1 r315
  text "PG3" at 69.41,39.99 h1.1 r315
  text "PD6" at 1.725,37.475 h1.1 r315
  text "MEM_LED2" at 62.41,37.475 h1.1 r315
  text "NC" at 8.45,37.45 h1.1 r315
  text "PD10" at 69.41,37.45 h1.1 r315
  text "PC0" at 1.725,34.935 h1.1 r315
  text "MEM_GPIO" at 62.41,34.935 h1.1 r315
  text "NC" at 8.45,34.91 h1.1 r315
  text "PE4" at 69.41,34.91 h1.1 r315
  text "PB10" at 1.725,32.395 h1.1 r315
  text "NC" at 62.41,32.395 h1.1 r315
  text "NC" at 8.45,32.37 h1.1 r315
  text "PG7" at 69.41,32.37 h1.1 r315
  text "PD0" at 1.725,29.855 h1.1 r315
  text "NC" at 62.41,29.855 h1.1 r315
  text "NC" at 8.45,29.83 h1.1 r315
  text "NC" at 69.41,29.83 h1.1 r315
  text "PB2" at 1.725,27.315 h1.1 r315
  text "NC" at 62.41,27.315 h1.1 r315
  text "NC" at 8.45,27.29 h1.1 r315
  text "NC" at 69.41,27.29 h1.1 r315
  text "PF10" at 1.725,24.775 h1.1 r315
  text "NC" at 62.41,24.775 h1.1 r315
  text "NC" at 8.45,24.75 h1.1 r315
  text "NC" at 69.41,24.75 h1.1 r315
  text "PB5" at 1.725,22.235 h1.1 r315
  text "NC" at 62.41,22.235 h1.1 r315
  text "NC" at 8.45,22.21 h1.1 r315
  text "NC" at 69.41,22.21 h1.1 r315
  text "NC" at 1.725,19.695 h1.1 r315
  text "NC" at 62.41,19.695 h1.1 r315
  text "NC" at 8.45,19.67 h1.1 r315
  text "NC" at 69.41,19.67 h1.1 r315
  text "NC" at 1.725,17.155 h1.1 r315
  text "NC" at 62.41,17.155 h1.1 r315
  text "NC" at 8.45,17.13 h1.1 r315
  text "NC" at 69.41,17.13 h1.1 r315
  text "NC" at 1.725,14.615 h1.1 r315
  text "NC" at 62.41,14.615 h1.1 r315
  text "NC" at 8.45,14.59 h1.1 r315
  text "NC" at 69.41,14.59 h1.1 r315
  text "USB" at 20.628,13.518 h1.6
  text "ETHERNET" at 53.537,13.5 h1.6
  text "CN12" at 67.42,12.47 h1.5
  text "CN11" at 6.282,12.445 h1.5
  text "GND" at 4.774,7.122 h1.52
  text "GND" at 68.147,7.122 h1.52
  text ".GBO" at 31.238,-16.454 h3
  text ".Layer_Name" at 72.552,-16.454 h3
Top Paste:
  text ".Layer_Name" at 0.719,-16.412 h3
  text ".GTP" at 42.414,-16.412 h3
Bottom Paste:
  text ".GBP" at 31.129,-16.439 h3
  text ".Layer_Name" at 72.443,-16.439 h3
Top Solder:
  region: 25.175,9.6 25.175,1.1 27.175,1.1 27.175,9.6
  text ".Layer_Name" at 0.744,-16.487 h3
  text ".GTS" at 42.439,-16.487 h3
Bottom Solder:
  region: 25.175,9.6 25.175,1.1 27.175,1.1 27.175,9.6
  text ".GBS" at 31.154,-16.514 h3
  text ".Layer_Name" at 72.468,-16.514 h3
M1-Board Shape:
  lines w0.1: 68,0 ccw(c68,2) 70,2 70,131.34 ccw(c68,131.34) 68,133.34 2,133.34 ccw(c2,131.34) 0,131.34 0,2 ccw(c2,2) 2,0 40.22,0 43.345,0 43.345,6.458 cw(c43.345,7.358) 42.445,7.358 cw(c43.345,7.358) 43.345,8.258 57.192,8.257 cw(c57.192,7.357) 58.092,7.357 cw(c57.192,7.357) 57.192,6.457 57.192,0 68,0 ; 68,0 68,0
M2-Board Dimensions:
  text ".Layer_Name" at 0.747,-16.422 h3
  text ".GM2" at 42.441,-16.422 h3
M14-Top Assembly:
  text ".Layer_Name" at 0.747,-16.422 h3
  text ".GM14" at 42.441,-16.422 h3
M15-Bottom Assembly:
  text ".GM15" at 31.238,-16.454 h3
  text ".Layer_Name" at 72.552,-16.454 h3
Drill Drawing:
  drawing of 678 lines, arcs and shapes, not listed
  text "THE COMPONENTS WITH PLATED THROUGH HOLE (PTH) MAY BE WELDED (CABLED) IN \"PIN-IN-PASTE\" MODE (IF NECESSARY)" at -15.075,189.275 h3.5
  text "PCB SPECIFICATIONS :" at -14.039,182.104 h3
  text "PCB : TYPE 3" at 144.498,180.872 h3
  text "A.   MATERIAL :" at -14.039,178.104 h3
  text "FR-4" at 24.461,178.104 h3
  text "TG-170" at 40.961,178.104 h3
  text "X  TG-150" at 59.211,178.104 h3
  text "TG-140" at 75.211,178.104 h3
  text "ASPECT-RATIO, AXE Z :" at 144.498,175.372 h3
  text "B.   MATERIAL FAMILY :" at -14.039,175.104 h3
  text "N/A" at 24.461,175.104 h3
  text "C.   SOLDERMASK COLOR :" at -14.039,172.104 h3
  text "GREEN" at 24.461,172.104 h3
  text "X  WHITE" at 40.961,172.104 h3
  text "RED" at 59.211,172.104 h3
  text "BLACK" at 75.211,172.104 h3
  text "D.   SILKSCREEN COLOR :" at -14.039,169.104 h3
  text "WHITE" at 24.461,169.104 h3
  text "YELLOW" at 40.961,169.104 h3
  text "BLACK" at 59.211,169.104 h3
  text "X  Blue ink PANTONE 2955" at 75.211,169.104 h3
  text "6:1 to 8:1 / LEVEL \"B\"" at 144.516,168.624 h3
  text "E.   SURFACE FINISH :" at -14.039,166.104 h3
  text "X  ENIG" at 24.461,166.104 h3
  text "IMMERSION SILVER" at 40.961,166.104 h3
  text "IMMERSION TIN" at 75.211,166.104 h3
  text "HASL" at 24.461,163.104 h3
  text "HASL (PB-FREE)" at 40.961,163.104 h3
  text "GOLDEN FINGER" at 75.211,163.104 h3
  text "MINIMUM PARAMETERS" at 144.543,163.023 h3
  text "F.   IMPEDANCE CONTROL :" at -14.039,160.104 h3
  text "NO" at 24.461,160.104 h3
  text "X  YES  (SEE IMPEDANCE TABLE FOR DETAIL INFORMATION)" at 40.961,160.104 h3
  text "DEFAULT" at 144.543,157.523 h3
  text "G.   THROUGH VIA :" at -14.039,157.104 h3
  text "PLUG THE VIAS WHICH ARE COVERED WITH SOLDERMASK ONE OR TWO SIDE." at 24.461,157.104 h3
  text "PLUG MATERIAL :" at 24.461,154.104 h3
  text "X  SOLDERMASK" at 49.961,154.104 h3
  text "NON-CONDUCTIVE EPOXY." at 75.211,154.104 h3
  text "TRACKS : 0.120mm           / GAPS : 0.120mm" at 144.543,151.773 h3
  text "H.   STACK-UP :" at -14.039,151.104 h3
  text "SEE LAYER STACK-UP SEQUENCE FOR OVERALL THICKNESS." at 24.461,151.104 h3
  text "Layer" at 98.804,124.321 h1.52
  text "Name" at 105.182,124.321 h1.52
  text "Material" at 117.516,124.321 h1.52
  text "Thickness" at 128.599,124.321 h1.52
  text "Constant" at 137.703,124.321 h1.52
  text "Board Layer Stack" at 146.129,124.321 h1.52
  text "Board Layer Stack" at 160.291,124.321 h1.52
  text "Top Overlay" at 105.182,121.273 h1.52
  text "Top Solder" at 105.182,118.225 h1.52
  text "Solder Resist" at 117.516,118.225 h1.52
  text "0,59mil" at 128.599,118.225 h1.52
  text "3.5" at 137.703,118.225 h1.52
  text "1" at 98.804,115.177 h1.52
  text "Top Layer" at 105.182,115.177 h1.52
  text "1,65mil" at 128.599,115.177 h1.52
  text "Dielectric 1" at 105.182,112.129 h1.52
  text "FR-4" at 117.516,112.129 h1.52
  text "3,54mil" at 128.599,112.129 h1.52
  text "4.2" at 137.703,112.129 h1.52
  text "2" at 98.803,109.081 h1.52
  text "Signal Layer 1" at 105.182,109.081 h1.52
  text "1,38mil" at 128.599,109.081 h1.52
  text "Dielectric 2" at 105.182,106.033 h1.52
  text "FR-4" at 117.516,106.033 h1.52
  text "3,94mil" at 128.599,106.033 h1.52
  text "4.2" at 137.703,106.033 h1.52
  text "3" at 98.804,102.985 h1.52
  text "Signal Layer 2" at 105.182,102.985 h1.52
  text "1,38mil" at 128.599,102.985 h1.52
  text "Dielectric 3" at 105.182,99.937 h1.52
  text "FR4" at 117.516,99.937 h1.52
  text "38,03mil" at 128.599,99.937 h1.52
  text "4.2" at 137.703,99.937 h1.52
  text "4" at 98.804,96.889 h1.52
  text "Signal Layer 3" at 105.182,96.889 h1.52
  text "1,38mil" at 128.599,96.889 h1.52
  text "Dielectric4" at 105.182,93.841 h1.52
  text "FR-4" at 117.516,93.841 h1.52
  text "3,94mil" at 128.599,93.841 h1.52
  text "4.2" at 137.703,93.841 h1.52
  text "5" at 98.804,90.793 h1.52
  text "Signal Layer 4" at 105.182,90.793 h1.52
  text "1,38mil" at 128.599,90.793 h1.52
  text "Dielectric5" at 105.182,87.745 h1.52
  text "FR-4" at 117.516,87.745 h1.52
  text "3,54mil" at 128.599,87.745 h1.52
  text "4.2" at 137.703,87.745 h1.52
  text "6" at 98.804,84.697 h1.52
  text "Bottom Layer" at 105.182,84.697 h1.52
  text "1,65mil" at 128.599,84.697 h1.52
  text "Bottom Solder" at 105.182,81.649 h1.52
  text "Solder Resist" at 117.516,81.649 h1.52
  text "0,59mil" at 128.599,81.649 h1.52
  text "3.5" at 137.703,81.649 h1.52
  text "Bottom Overlay" at 105.182,78.601 h1.52
  text "Symbol" at 79.177,51.191 h1.83
  text "Count" at 86.338,51.191 h1.83
  text "Hole Size" at 94.431,51.191 h1.83
  text "Plated" at 109.145,51.191 h1.83
  text "Hole Type" at 115.431,51.191 h1.83
  text "Drill Layer Pair" at 124.582,51.191 h1.83
  text "Via/Pad" at 141.925,51.191 h1.83
  text "Pad Shape" at 149.424,51.191 h1.83
  text "Template" at 159.219,51.191 h1.83
  text "Hole Length" at 180.446,51.191 h1.83
  text "Routed Path Length" at 194.377,51.191 h1.83
  text "8" at 86.338,48.037 h1.52
  text "0.500mm (19.69mil)" at 94.431,48.037 h1.52
  text "PTH" at 109.145,48.037 h1.52
  text "Slot" at 115.431,48.037 h1.52
  text "Top Layer - Bottom Layer" at 124.582,48.037 h1.52
  text "Pad" at 141.925,48.037 h1.52
  text "Rounded" at 149.424,48.037 h1.52
  text "r140_80h50_110r40m150_90" at 159.219,48.037 h1.52
  text "1.100mm (43.31mil)" at 180.446,48.037 h1.52
  text "0.600mm (23.62mil)" at 194.377,48.037 h1.52
  text "2" at 86.338,44.882 h1.52
  text "0.650mm (25.59mil)" at 94.431,44.882 h1.52
  text "NPTH" at 109.145,44.882 h1.52
  text "Round" at 115.431,44.882 h1.52
  text "Top Layer - Bottom Layer" at 124.582,44.882 h1.52
  text "Pad" at 141.925,44.882 h1.52
  text "Rounded" at 149.424,44.882 h1.52
  text "c0hn65m10" at 159.219,44.882 h1.52
  text "-" at 180.446,44.882 h1.52
  text "-" at 194.377,44.882 h1.52
  text "2" at 86.338,41.728 h1.52
  text "0.650mm (25.59mil)" at 94.431,41.728 h1.52
  text "NPTH" at 109.145,41.728 h1.52
  text "Slot" at 115.431,41.728 h1.52
  text "Top Layer - Bottom Layer" at 124.582,41.728 h1.52
  text "Pad" at 141.925,41.728 h1.52
  text "Rounded" at 149.424,41.728 h1.52
  text "c0hn65_95m10" at 159.219,41.728 h1.52
  text "0.950mm (37.40mil)" at 180.446,41.728 h1.52
  text "0.300mm (11.81mil)" at 194.377,41.728 h1.52
  text "12" at 86.338,38.574 h1.52
  text "0.700mm (27.56mil)" at 94.431,38.574 h1.52
  text "PTH" at 109.145,38.574 h1.52
  text "Round" at 115.431,38.574 h1.52
  text "Top Layer - Bottom Layer" at 124.582,38.574 h1.52
  text "Pad" at 141.925,38.574 h1.52
  text "(Mixed)" at 149.424,38.574 h1.52
  text "(Mixed)" at 159.219,38.574 h1.52
  text "-" at 180.446,38.574 h1.52
  text "-" at 194.377,38.574 h1.52
  text "2" at 86.338,35.42 h1.52
  text "0.700mm (27.56mil)" at 94.431,35.42 h1.52
  text "PTH" at 109.145,35.42 h1.52
  text "Slot" at 115.431,35.42 h1.52
  text "Top Layer - Bottom Layer" at 124.582,35.42 h1.52
  text "Pad" at 141.925,35.42 h1.52
  text "Rounded" at 149.424,35.42 h1.52
  text "r280_130h70_220r65m290_140" at 159.219,35.42 h1.52
  text "2.200mm (86.61mil)" at 180.446,35.42 h1.52
  text "1.500mm (59.06mil)" at 194.377,35.42 h1.52
  text "166" at 86.338,32.266 h1.52
  text "1.000mm (39.37mil)" at 94.431,32.266 h1.52
  text "PTH" at 109.145,32.266 h1.52
  text "Round" at 115.431,32.266 h1.52
  text "Top Layer - Bottom Layer" at 124.582,32.266 h1.52
  text "Pad" at 141.925,32.266 h1.52
  text "Rounded" at 149.424,32.266 h1.52
  text "(Mixed)" at 159.219,32.266 h1.52
  text "-" at 180.446,32.266 h1.52
  text "-" at 194.377,32.266 h1.52
  text "32" at 86.338,29.111 h1.52
  text "1.100mm (43.31mil)" at 94.431,29.111 h1.52
  text "PTH" at 109.145,29.111 h1.52
  text "Round" at 115.431,29.111 h1.52
  text "Top Layer - Bottom Layer" at 124.582,29.111 h1.52
  text "Pad" at 141.925,29.111 h1.52
  text "Rounded" at 149.424,29.111 h1.52
  text "(Mixed)" at 159.219,29.111 h1.52
  text "-" at 180.446,29.111 h1.52
  text "-" at 194.377,29.111 h1.52
  text "1" at 86.338,25.957 h1.52
  text "1.150mm (45.28mil)" at 94.431,25.957 h1.52
  text "NPTH" at 109.145,25.957 h1.52
  text "Round" at 115.431,25.957 h1.52
  text "Top Layer - Bottom Layer" at 124.582,25.957 h1.52
  text "Pad" at 141.925,25.957 h1.52
  text "Rounded" at 149.424,25.957 h1.52
  text "c0hn115m10" at 159.219,25.957 h1.52
  text "-" at 180.446,25.957 h1.52
  text "-" at 194.377,25.957 h1.52
  text "B" at 78.536,25.703 h1.4
  text "2" at 86.338,22.803 h1.52
  text "1.500mm (59.06mil)" at 94.431,22.803 h1.52
  text "NPTH" at 109.145,22.803 h1.52
  text "Round" at 115.431,22.803 h1.52
  text "Top Layer - Bottom Layer" at 124.582,22.803 h1.52
  text "Pad" at 141.925,22.803 h1.52
  text "Rounded" at 149.424,22.803 h1.52
  text "c0hn150m160(Tol3-3)" at 159.219,22.803 h1.52
  text "-" at 180.446,22.803 h1.52
  text "-" at 194.377,22.803 h1.52
  text "1" at 86.338,19.649 h1.52
  text "1.650mm (64.96mil)" at 94.431,19.649 h1.52
  text "NPTH" at 109.145,19.649 h1.52
  text "Round" at 115.431,19.649 h1.52
  text "Top Layer - Bottom Layer" at 124.582,19.649 h1.52
  text "Pad" at 141.925,19.649 h1.52
  text "Rounded" at 149.424,19.649 h1.52
  text "c0hn165m10" at 159.219,19.649 h1.52
  text "-" at 180.446,19.649 h1.52
  text "-" at 194.377,19.649 h1.52
  text "A" at 78.536,19.395 h1.4
  text "3" at 86.338,16.495 h1.52
  text "3.200mm (125.98mil)" at 94.431,16.495 h1.52
  text "NPTH" at 109.145,16.495 h1.52
  text "Round" at 115.431,16.495 h1.52
  text "Top Layer - Bottom Layer" at 124.582,16.495 h1.52
  text "Pad" at 141.925,16.495 h1.52
  text "Rounded" at 149.424,16.495 h1.52
  text "c320hn320" at 159.219,16.495 h1.52
  text "-" at 180.446,16.495 h1.52
  text "-" at 194.377,16.495 h1.52
  text "1" at 86.338,13.34 h1.52
  text "4.150mm (163.39mil)" at 94.431,13.34 h1.52
  text "PTH" at 109.145,13.34 h1.52
  text "Round" at 115.431,13.34 h1.52
  text "Top Layer - Bottom Layer" at 124.582,13.34 h1.52
  text "Pad" at 141.925,13.34 h1.52
  text "Rounded" at 149.424,13.34 h1.52
  text "c600h415m610" at 159.219,13.34 h1.52
  text "-" at 180.446,13.34 h1.52
  text "-" at 194.377,13.34 h1.52
  text "1373" at 86.338,10.186 h1.52
  text "0.350mm (13.78mil)" at 94.431,10.186 h1.52
  text "PTH" at 109.145,10.186 h1.52
  text "Round" at 115.431,10.186 h1.52
  text "Top Layer - Bottom Layer" at 124.582,10.186 h1.52
  text "Via" at 141.925,10.186 h1.52
  text "Rounded" at 149.424,10.186 h1.52
  text "v55h35m0mx0(1)" at 159.219,10.186 h1.52
  text "-" at 180.446,10.186 h1.52
  text "-" at 194.377,10.186 h1.52
  text "1605 Total" at 86.338,7.032 h1.52
  text "Slot definitions :" at 79.177,4.824 h1.52
  text "Routed Path Length" at 89.571,4.824 h1.52
  text "= Calculated from tool start centre position to tool end centre position." at 102.448,4.824 h1.52
  text "Hole Length" at 89.571,3.562 h1.52
  text "= Routed Path Length + Tool Size = Slot length as defined in the PCB layout" at 97.668,3.562 h1.52
  text ".Layer_Name" at 0.747,-16.422 h3
  text ".DRL" at 42.441,-16.422 h3
M20-Top Title Box:
  circle w0.254: c78.751,-23.143 r1.3
  region: 64.273,-24.236 53.517,-24.236 54.51,-21.743 62.368,-21.743 62.817,-20.984 65.025,-23.532
  region: 78.276,-15.906 62.749,-15.906 62.055,-17.682 60.844,-18.907 59.447,-17.047 59.447,-15.396 60.59,-13.999 62.026,-13.62 78.276,-13.62
  lines w0.254: 54.51,-21.743 63.302,-21.743 60.236,-18.205 cw(c62.04,-16.261) 62.28,-13.62 79.044,-13.62 78.282,-15.906 ; 57.824,-13.373 cw(c60.25,-14.344) 60.487,-11.741 ; 57.863,-13.341 53.517,-24.236 72.839,-24.236 ccw(c73.088,-21.501) 75.637,-22.521 ; 59.603,-17.275 65.025,-23.532 ; 59.857,-17.275 65.162,-23.397 ; 59.857,-17.021 65.162,-23.143 ; 59.955,-15.906 72.948,-15.906 ; 59.984,-16.894 65.289,-23.016 ; 60.111,-16.767 65.416,-22.889 ; 60.238,-16.64 65.543,-22.762 ; 60.365,-16.513 65.67,-22.635 ; 60.42,-14.561 65.725,-20.682 ; 60.488,-11.741 79.937,-11.741 75.638,-22.519 ; 60.492,-16.386 65.742,-22.445 ; 60.492,-16.132 65.797,-22.254 ; 60.492,-15.878 65.797,-22 ; 60.492,-14.989 65.797,-21.111 ; 60.619,-15.751 65.924,-21.873 ; 60.619,-15.37 65.924,-21.492 ; 61.991,-21.756 ccw(c62.096,-21.221) 62.393,-20.764 ; 63.077,-15.893 ccw(c63.051,-16.46) 62.721,-16.922 65.086,-19.651 cw(c63.282,-21.595) 64.014,-24.143 ; 69.358,-24.032 72.248,-15.652 ; 69.581,-23.982 72.45,-15.661 ; 69.708,-23.982 72.577,-15.661 ; 69.962,-23.982 72.831,-15.661 ; 70.216,-23.982 73.085,-15.661 ; 70.47,-23.982 73.339,-15.661 ; 70.724,-23.982 73.593,-15.661 ; 70.978,-23.982 73.847,-15.661 ; 71.232,-23.982 74.101,-15.661 ; 71.486,-23.982 74.355,-15.661 ; 71.694,-24.032 74.584,-15.652 ; 74.584,-15.906 78.276,-15.906 ; 77.608,-15.904 78.37,-13.618 ; 77.774,-15.906 78.536,-13.62 ; 78.028,-15.906 78.79,-13.62
  lines w0.3: -8.254,-28.122 81.746,-28.122 81.746,-8.122 -8.254,-8.122 ; -8.254,-23.122 51.746,-23.122 ; -8.254,-18.122 51.746,-18.122 ; -8.254,-13.122 51.746,-13.122 ; -8.253,-28.122 -8.253,-8.122 ; 31.746,-28.122 31.746,-13.122 ; 51.746,-28.122 51.746,-8.122 ; 69.358,-24.032 71.694,-24.032
  text "Project: '.Board_Name'" at -7.253,-11.338 h3
  text "Layer:" at -7.253,-16.422 h3
  text "Gerber:" at 32.735,-16.422 h3
  text "Variant: '.VariantName'" at -7.253,-21.422 h3
  text "'.Board_Reference'" at 32.862,-21.422 h3
  text "R" at 78.243,-23.905 h1.52
  text "Date: '.Board_Document_Date'" at -7.253,-26.422 h3
  text "Rev: '.Board_PCB_Revision'" at 32.805,-26.422 h3
M21-Bottom Title Box:
  circle w0.254: c-5.071,-23.143 r1.3
  region: -4.596,-15.906 10.931,-15.906 11.626,-17.682 12.836,-18.907 14.233,-17.047 14.233,-15.396 13.09,-13.999 11.654,-13.62 -4.596,-13.62
  region: 9.407,-24.236 20.163,-24.236 19.17,-21.743 11.312,-21.743 10.864,-20.984 8.655,-23.532
  lines w0.254: -5.11,-13.62 -4.348,-15.906 ; -4.856,-13.62 -4.094,-15.906 ; -4.69,-13.618 -3.928,-15.904 ; -4.602,-15.906 -5.364,-13.62 11.4,-13.62 cw(c11.64,-16.261) 13.444,-18.205 10.378,-21.743 19.17,-21.743 ; -4.596,-15.906 -0.904,-15.906 ; -1.958,-22.519 -6.257,-11.741 13.192,-11.741 ; -1.957,-22.521 ccw(c0.592,-21.501) 0.841,-24.236 20.163,-24.236 15.817,-13.341 ; -0.904,-15.652 1.986,-24.032 ; -0.675,-15.661 2.194,-23.982 ; -0.421,-15.661 2.448,-23.982 ; -0.167,-15.661 2.702,-23.982 ; 0.087,-15.661 2.956,-23.982 ; 0.341,-15.661 3.21,-23.982 ; 0.595,-15.661 3.464,-23.982 ; 0.732,-15.906 13.725,-15.906 ; 0.849,-15.661 3.718,-23.982 ; 1.103,-15.661 3.972,-23.982 ; 1.23,-15.661 4.099,-23.982 ; 1.432,-15.652 4.322,-24.032 ; 7.756,-21.873 13.061,-15.751 ; 7.756,-21.492 13.061,-15.37 ; 7.883,-22.254 13.188,-16.132 ; 7.883,-22 13.188,-15.878 ; 7.883,-21.111 13.188,-14.989 ; 7.938,-22.445 13.188,-16.386 ; 7.956,-20.682 13.261,-14.561 ; 8.01,-22.635 13.315,-16.513 ; 8.137,-22.762 13.442,-16.64 ; 8.264,-22.889 13.569,-16.767 ; 8.391,-23.016 13.696,-16.894 ; 8.518,-23.397 13.823,-17.275 ; 8.518,-23.143 13.823,-17.021 ; 8.655,-23.532 14.077,-17.275 ; 9.666,-24.143 cw(c10.398,-21.595) 8.594,-19.651 10.959,-16.922 ccw(c10.629,-16.46) 10.603,-15.893 ; 11.287,-20.764 ccw(c11.585,-21.221) 11.69,-21.756 ; 13.194,-11.741 cw(c13.43,-14.344) 15.856,-13.373
  lines w0.3: 1.986,-24.032 4.322,-24.032 ; 21.746,-28.122 21.746,-8.122 ; 21.746,-23.122 81.746,-23.122 ; 21.746,-18.122 81.746,-18.122 ; 21.746,-13.122 81.746,-13.122 ; 41.746,-28.122 41.746,-13.122 ; -8.254,-28.122 -8.254,-8.122 81.746,-8.122 81.746,-28.122 -8.254,-28.122
  text "Project: '.Board_Name'" at 80.552,-11.338 h3
  text "Gerber:" at 40.564,-16.422 h3
  text "Layer:" at 80.552,-16.422 h3
  text "'.Board_Reference'" at 40.564,-21.422 h3
  text "Variant: '.VariantName'" at 80.552,-21.422 h3
  text "R" at -4.563,-23.905 h1.52
  text "Rev: '.Board_PCB_Revision'" at 40.621,-26.422 h3
  text "Date: '.Board_Document_Date'" at 80.552,-26.422 h3

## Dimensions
59.126,73.67 to 59.126,77.734 on M3-Top Dimensions
59.126,100.594 to 68,133.34 on M3-Top Dimensions
10.866,68.59 to 10.866,73.67 on M3-Top Dimensions
10.866,91.45 to 2,133.34 on M3-Top Dimensions
66.746,101.61 to 68,133.34 on M3-Top Dimensions
3.246,101.61 to 2,133.34 on M3-Top Dimensions
59.126,104.15 to 68,133.34 on M3-Top Dimensions
10.866,105.42 to 2,133.34 on M3-Top Dimensions
10.866,105.42 to 59.126,104.15 on M3-Top Dimensions
64.206,15.25 to 70,2 on M3-Top Dimensions
5.786,15.25 to 0,0 on M3-Top Dimensions
5.786,15.25 to 64.206,15.25 on M3-Top Dimensions
10.866,55.89 to 59.126,55.89 on M3-Top Dimensions
3.246,129.55 to 66.746,129.55 on M3-Top Dimensions
0,131.34 to 70,131.34 on M2-Board Dimensions
2,0 to 2,133.34 on M2-Board Dimensions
